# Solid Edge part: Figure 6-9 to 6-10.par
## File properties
Author: CADCIM
Template: normal.par
Last saved by: CADCIM
Revision: 7
Application: Solid Edge
Accuracy: 0.99
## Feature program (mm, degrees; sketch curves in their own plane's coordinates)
sketch for "unnamed Protrusion 1" plane through (0, 0, 0) normal (0, 0, 1) x-axis (1, 0, 0)
  line (-22.8701, -37.8701) -> (22.8701, -37.8701)
  arc centre (22.8701, -22.8701) radius 15 from (22.8701, -37.8701) to (37.8701, -22.8701) ccw
  line (37.8701, -22.8701) -> (37.8701, 22.8701)
  arc centre (22.8701, 22.8701) radius 15 from (37.8701, 22.8701) to (22.8701, 37.8701) ccw
  line (22.8701, 37.8701) -> (-22.8701, 37.8701)
  arc centre (-22.8701, 22.8701) radius 15 from (-22.8701, 37.8701) to (-37.8701, 22.8701) ccw
  line (-37.8701, 22.8701) -> (-37.8701, -22.8701)
  arc centre (-22.8701, -22.8701) radius 15 from (-22.8701, -37.8701) to (-37.8701, -22.8701) cw
extrude "unnamed Protrusion 1" add finite 20 along +normal
sketch for "Hole_3" plane through (0, 0, 20) normal (0, 0, 1) x-axis (0, 1, 0)
  hole centre (-22.8701, 22.8701) bore radius 4.5
hole "Hole_3" diameter 9 through  CounterBoreDepth = 5 mm
sketch for "unnamed Hole 1" plane through (0, 0, 20) normal (0, 0, 1) x-axis (0, 1, 0)
  hole centre (22.8701, 22.8701) bore radius 4.5
hole "unnamed Hole 1" through
sketch for "unnamed Hole 2" plane through (0, 0, 20) normal (0, 0, 1) x-axis (0, 1, 0)
  hole centre (22.8701, -22.8701) bore radius 4.5
hole "unnamed Hole 2" through
sketch for "unnamed Hole 3" plane through (0, 0, 20) normal (0, 0, 1) x-axis (0, 1, 0)
  hole centre (-22.8701, -22.8701) bore radius 4.5
hole "unnamed Hole 3" through
pattern "unnamed Pattern 1" of "Hole_3", "unnamed Hole 1", "unnamed Hole 2", "unnamed Hole 3"
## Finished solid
Body 1: solid body, 22 faces, 40 edges, 16 vertices.
  Faces by surface: cylinder 12, plane 10
  Edges by curve: circle 24, line 16
Bounding box of the edges (mm): 75.740 x 75.740 x 20.000, from (-37.8701, -37.8701, 0) to (37.8701, 37.8701, 20).
Cylindrical faces by radius (mm): R4.5 x4, R7.5 x4, R15 x4
Planar faces by outward normal: +x 1, +y 1, +z 5, -x 1, -y 1, -z 1
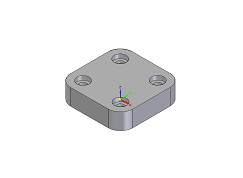
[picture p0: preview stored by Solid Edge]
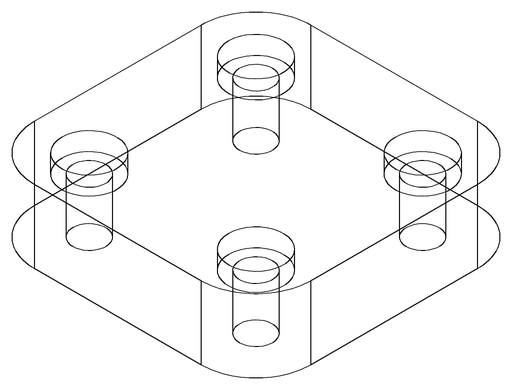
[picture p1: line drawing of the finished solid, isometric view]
